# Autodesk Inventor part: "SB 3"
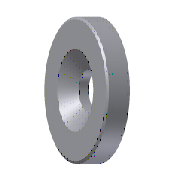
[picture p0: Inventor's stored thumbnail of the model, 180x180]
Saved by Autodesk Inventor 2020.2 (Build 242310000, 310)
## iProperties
IsCustomPart: 0
Manager: www.cadconsulting.pl
Company: Fabian Stasiak CAD Consulting
Created: 2014-02
Part Number: "SB 3"
Material: DIN 1.2312
Description: Spacer washer for ejector plates
Document SubType Name: Modeling
Designer: F.Stasiak
Standard Revision: 1
Manufacturer: DME
Language: pl-PL
Size Designation: " 3"
Categories: <MemberInstance><Categories><Category DisplayName="Forma wtryskowa" InternalName="349578f2-f4d4-4954-8c09-8e99297a61c0" Mnemonic="MOLD"><Category DisplayName="A
Density: 7.85 g/cm^3
Appearance: Domyślna
Catalog Web Link: www.expertbooks.pl
Author: F.Stasiak
Subject: Zbiór ćwiczeń. Autodesk Inventor 2020. Kurs Professional
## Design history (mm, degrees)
sketch "Sketch1"
  geometry: L1 (0, -0.8)-(0, 4.8) reference; L2 (2.25, 1.5)-(4.75, 4); L3 (4.75, 4)-(13, 4); L4 (13, 4)-(13, 0); L5 (13, 0)-(2.25, 0); L6 (2.25, 0)-(2.25, 1.5); 1 further point
  constraints: 10 end point, 4 perpendicular, 1 horizontal alignment
  dimensions: "d0" = 45 deg angle of L2 L1 (= A_); "d1" = 9.5 diameter of L2.end L1 (= Sink_Dia); "d2" = 26 diameter of L4 L1 (= D); "d3" = 4 distance between parallel lines of L5 L3 (= H1); "d4" = 4.5 diameter of L6 L1 (= d_)
revolve "Revolution1" sketch "Sketch1" stored, may be unused: angle "d5" = 90 deg
chamfer "Chamfer1" distance "d6" = 0.3; stored, may be unused: second distance "d7" = 2, angle "d8" = 45 deg
body "Solid1"
other parameters: "D" = 26 [user parameter; used in 1 equation term], "H1" = 4 [user parameter; used in 1 equation term], "d_" = 4.5 [user parameter; used in 1 equation term], "Sink_Dia" = 9.5 [user parameter; used in 1 equation term], "d9" = 0, "d10" = 0, "d11" = 0, "A_" = 45 deg [user parameter; used in 1 equation term]
